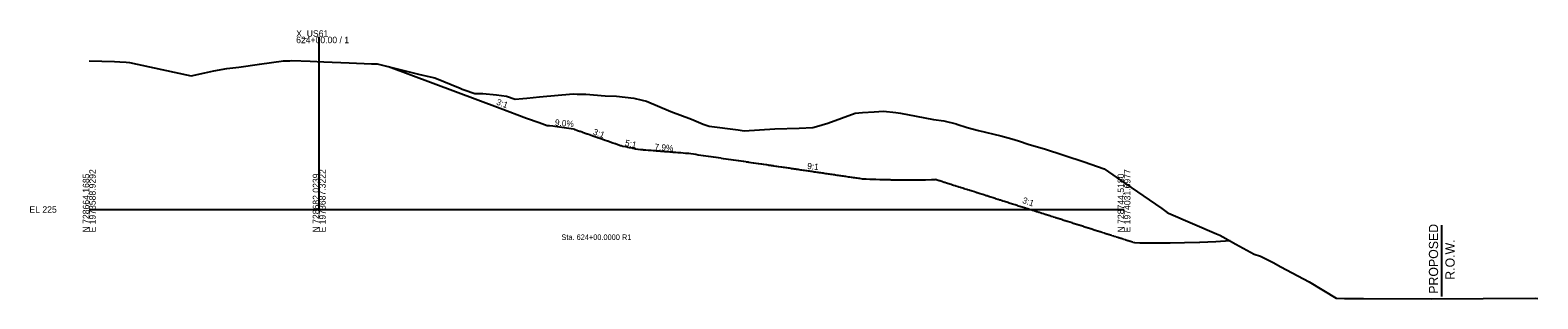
# Model space of a CAD drawing. Extents: x -26 to 630, y -39 to 9098.
# Drawn here: x -26 to 630, y -39 to 78 of the extents above; entities that cross this region are included whole.
import ezdxf

# ---------------------------------------------------------------- set-up
doc = ezdxf.new("R2010")
doc.units = 0
for name, color, linetype in [('CONST_DCH', 7, 'Continuous'), ('Default', 7, 'Continuous'), ('Draft_XS_Grid', 7, 'Continuous'), ('Draft_XS_Text', 7, 'Continuous'), ('DTM_X_FLOW_ARROWS', 7, 'Continuous'), ('DTM_X_GROUND', 7, 'Continuous'), ('XS_CELL', 7, 'Continuous'), ('XS_P_GROUND', 7, 'Continuous'), ('XS_P_ROW', 7, 'Continuous'), ('XS_P_TX_FS_BS', 7, 'Continuous')]:
    doc.layers.add(name, color=color, linetype=linetype)

msp = doc.modelspace()

# ---------------------------------------------------------------- linework, layer by layer
at = {"layer": 'DTM_X_GROUND'}
msp.add_lwpolyline([(0, 64.48), (10.96, 64.2), (13.31, 64.15), (16.1, 63.91), (17.53, 63.79), (20.8, 63.08), (44.32, 58.06), (50.31, 59.32), (54.16, 60.13), (59.81, 61.19), (65.07, 61.81), (74.07, 63.05), (84.46, 64.48), (87.2, 64.59), (88.13, 64.63), (96.02, 64.37), (102, 64.17), (113.06, 63.68), (122.74, 63.25), (123.28, 63.24), (125.23, 63.19), (143.22, 58.82), (148.23, 57.66), (150.24, 57.15), (161.3, 52.65), (162.21, 52.3), (163.05, 51.98), (167.75, 50.3), (171.13, 50.4), (177.05, 49.82), (181.48, 49.14), (185.25, 47.91), (188.63, 48.18), (190.36, 48.32), (195.82, 48.85), (210.42, 50.18), (212.18, 50.12), (215.92, 50.01), (224.35, 49.34), (229.31, 49.18), (236.83, 48.34), (240.5, 47.48), (242.4, 47.03), (252.93, 42.49), (261.95, 39.24), (266.97, 37.11), (269.53, 36.23), (282.23, 34.55), (284.75, 34.21), (298.13, 34.97), (308.68, 35.33), (314.62, 35.55), (316.28, 36.04), (321.16, 37.49), (333.03, 41.83), (336.21, 42.06), (341.37, 42.44), (345.38, 42.75), (350.7, 42.06), (352.78, 41.8), (359.57, 40.51), (367.19, 39.01), (371.71, 38.42), (376.94, 37.13), (377.24, 37.03), (381.86, 35.59), (386.79, 34.35), (396.4, 32.02), (401.21, 30.65), (404.1, 29.78), (408.75, 28.22), (415.35, 26.37), (432.61, 20.7), (441.38, 17.61), (450.42, 11.4), (466.46, 0.38), (468.82, -1.32), (469.36, -1.66), (490.18, -10.6), (491.62, -11.17), (492.92, -11.9), (498.61, -15.09), (506.62, -19.39), (509.37, -20.29), (514.9, -23.06), (518.23, -24.95), (530.49, -31.39), (542.25, -38.58), (545.81, -38.59), (550.25, -38.61), (551.07, -38.62), (553.13, -38.68), (554.11, -38.68), (583.63, -38.79), (628.84, -38.52), (629.96, -38.61)], dxfattribs=at)
at = {"layer": 'XS_CELL'}
for p, q in [((100, 0), (100, 75)), ((0, 0), (100, 0)), ((100, 0), (450, 0))]:
    msp.add_line(p, q, dxfattribs=at)
at = {"layer": 'XS_P_GROUND'}
for points in [[(130.08, 62.01), (178.64, 43.98), (190.22, 39.64), (195.63, 37.81), (199.21, 36.5)], [(199.21, 36.5), (200.07, 36.47), (200.11, 36.47), (201.64, 36.29), (202.53, 36.17)], [(202.53, 36.17), (210.65, 34.94), (210.65, 34.94), (210.65, 34.94), (211.08, 34.79), (211.28, 34.72), (212.06, 34.45), (212.37, 34.34), (213.18, 34.06), (213.47, 33.96), (214.3, 33.66), (214.56, 33.57), (215.42, 33.27), (215.66, 33.19), (216.54, 32.88), (216.75, 32.81), (217.66, 32.49), (217.85, 32.42), (218.77, 32.1), (218.94, 32.04), (219.88, 31.71), (220.03, 31.66), (221, 31.32), (221.13, 31.27), (222.11, 30.93), (222.22, 30.89), (223.22, 30.54), (223.32, 30.51), (224.33, 30.15), (224.41, 30.12), (225.44, 29.77), (225.51, 29.74), (226.55, 29.38), (226.6, 29.36), (227.66, 28.99), (227.7, 28.98), (228.76, 28.6), (228.79, 28.59), (229.87, 28.21), (229.89, 28.21), (230.98, 27.83), (230.98, 27.83), (231.29, 27.72), (232.08, 27.55), (232.21, 27.52), (233.17, 27.31), (233.88, 27.16), (234.27, 27.08), (234.79, 26.97), (235.36, 26.85), (236.07, 26.69), (236.46, 26.61), (236.74, 26.55), (237.55, 26.38), (238.64, 26.14), (238.64, 26.14), (238.66, 26.14)], [(238.66, 26.14), (239.74, 26.05), (239.8, 26.05), (240.83, 25.97), (240.95, 25.96), (241.93, 25.88), (242.1, 25.87), (243.02, 25.79), (243.25, 25.78), (244.12, 25.71), (244.4, 25.69), (245.21, 25.62), (245.55, 25.6), (246.31, 25.54), (246.71, 25.5), (247.4, 25.45), (247.86, 25.41), (248.5, 25.36), (249.01, 25.32), (249.59, 25.28), (250.16, 25.23), (250.69, 25.19), (251.31, 25.14), (251.78, 25.1), (252.46, 25.05), (252.88, 25.02), (253.62, 24.96), (253.97, 24.93), (254.77, 24.87), (255.07, 24.85), (255.92, 24.78), (256.16, 24.76), (257.07, 24.69), (257.25, 24.67), (258.22, 24.6), (258.35, 24.59), (259.37, 24.51), (259.44, 24.5), (260.53, 24.42), (260.54, 24.41), (260.78, 24.4), (261.63, 24.27), (261.63, 24.27), (262.71, 24.11), (262.73, 24.11), (263.79, 23.95), (263.82, 23.95), (264.88, 23.79), (264.92, 23.79), (265.96, 23.64), (266.01, 23.63), (267.05, 23.48), (267.11, 23.47), (268.13, 23.32), (268.2, 23.31), (269.22, 23.16), (269.3, 23.15), (270.3, 23), (270.39, 22.99), (271.39, 22.84), (271.49, 22.83), (272.47, 22.68), (272.58, 22.67), (273.55, 22.52), (273.68, 22.51), (274.64, 22.36), (274.77, 22.34), (275.72, 22.2), (275.87, 22.18), (276.81, 22.05), (276.96, 22.02), (277.89, 21.89), (278.05, 21.86), (278.98, 21.73), (279.15, 21.7), (280.06, 21.57), (280.24, 21.54), (281.15, 21.41), (281.34, 21.38), (282.24, 21.25), (282.43, 21.22), (283.32, 21.09), (283.53, 21.06), (284.41, 20.93), (284.62, 20.9), (285.49, 20.77), (285.72, 20.74), (286.58, 20.61), (286.81, 20.58), (287.66, 20.45), (287.91, 20.42), (288.75, 20.3), (289, 20.26), (289.83, 20.14), (290.1, 20.1), (290.92, 19.98), (291.19, 19.94), (292, 19.82), (292.29, 19.78), (293.09, 19.66), (293.38, 19.62), (294.18, 19.5), (294.48, 19.46), (295.26, 19.34), (295.57, 19.3), (296.35, 19.18), (296.66, 19.14), (297.43, 19.02), (297.76, 18.97), (298.52, 18.86), (298.85, 18.81), (299.61, 18.7), (299.95, 18.65), (300.69, 18.54), (301.04, 18.49), (301.78, 18.39), (302.14, 18.33), (302.86, 18.23), (303.23, 18.17), (303.95, 18.07), (304.33, 18.01), (305.04, 17.91), (305.42, 17.85), (306.12, 17.75), (306.52, 17.69), (307.21, 17.59), (307.61, 17.53), (308.3, 17.43), (308.71, 17.37), (309.38, 17.27), (309.8, 17.21), (310.47, 17.11), (310.9, 17.05), (311.56, 16.95), (311.99, 16.89), (312.64, 16.79), (313.09, 16.73), (313.73, 16.63), (314.18, 16.57), (314.82, 16.47), (315.27, 16.41), (315.9, 16.31), (316.37, 16.25), (316.99, 16.16), (317.46, 16.09), (318.08, 16), (318.56, 15.93), (319.16, 15.84), (319.65, 15.77), (320.25, 15.68), (320.75, 15.6), (321.34, 15.52), (321.84, 15.44), (322.42, 15.36), (322.94, 15.28), (323.51, 15.2), (324.03, 15.12), (324.6, 15.04), (325.13, 14.96), (325.69, 14.88), (326.22, 14.8), (326.77, 14.72), (327.32, 14.64), (327.86, 14.56), (328.41, 14.48), (328.95, 14.4), (329.51, 14.32), (330.03, 14.24), (330.6, 14.16), (331.36, 14.05), (331.7, 14), (332.28, 13.91), (332.79, 13.84), (333.38, 13.75), (333.88, 13.68), (334.49, 13.59), (334.98, 13.52), (335.59, 13.43), (336.07, 13.36), (336.2, 13.34), (336.3, 13.32), (337.47, 13.3), (337.92, 13.25), (339.45, 13.22), (340, 13.16), (341.61, 13.14), (342.12, 13.09), (343.8, 13.07), (344.29, 13.02), (346.05, 13), (346.5, 12.97), (348.35, 12.95), (348.76, 12.92), (350.71, 12.91), (351.08, 12.89), (353.13, 12.89), (353.45, 12.86), (355.62, 12.87), (355.89, 12.85), (358.17, 12.87), (358.39, 12.85), (360.8, 12.88), (360.97, 12.87), (363.52, 12.91), (363.62, 12.9), (366.32, 12.95), (366.36, 12.95), (367.96, 12.98)], [(496.13, -13.64), (490, -14.01), (489.9, -14.01), (483.03, -14.33), (482.83, -14.33), (476.34, -14.54), (470.1, -14.65), (469.83, -14.66), (463.62, -14.68), (463.39, -14.68), (457.12, -14.6), (456.92, -14.6), (454.74, -14.53), (454.65, -14.52), (453.9, -14.28), (453.64, -14.2), (452.88, -13.96), (452.63, -13.88), (451.86, -13.64), (451.62, -13.56), (450.85, -13.32), (450.61, -13.24), (449.83, -12.99), (449.6, -12.92), (448.81, -12.67), (448.59, -12.6), (447.79, -12.35), (447.58, -12.28), (447.38, -12.22), (447.33, -12.2), (446.72, -12.01), (446.57, -11.96), (446.47, -11.93), (446.44, -11.92), (445.73, -11.69), (445.56, -11.64), (444.74, -11.38), (444.55, -11.32), (443.72, -11.05), (443.54, -11), (442.7, -10.73), (442.53, -10.68), (441.68, -10.41), (441.52, -10.36), (440.66, -10.08), (440.51, -10.04), (439.65, -9.76), (439.5, -9.72), (438.63, -9.44), (438.49, -9.4), (437.61, -9.11), (437.48, -9.08), (436.59, -8.79), (436.47, -8.76), (435.57, -8.47), (435.46, -8.43), (434.55, -8.14), (434.45, -8.11), (433.53, -7.82), (433.44, -7.79), (432.51, -7.5), (432.43, -7.47), (431.49, -7.17), (431.42, -7.15), (430.47, -6.85), (430.41, -6.83), (429.45, -6.53), (429.4, -6.51), (428.43, -6.2), (428.39, -6.19), (427.41, -5.88), (427.38, -5.87), (426.38, -5.55), (426.37, -5.55), (425.36, -5.23), (425.36, -5.23), (425.31, -5.21), (424.35, -4.91), (424.33, -4.9), (423.34, -4.59), (423.3, -4.57), (422.33, -4.27), (422.27, -4.25), (421.32, -3.95), (421.24, -3.92), (420.31, -3.63), (420.3, -3.62), (420.18, -3.59), (420.09, -3.56), (419.3, -3.31), (419.18, -3.27), (418.29, -2.99), (418.15, -2.94), (417.28, -2.67), (417.12, -2.61), (416.27, -2.35), (416.09, -2.29), (415.26, -2.02), (415.06, -1.96), (414.25, -1.7), (414.03, -1.63), (413.24, -1.38), (413, -1.31), (412.23, -1.06), (411.96, -0.98), (411.22, -0.74), (410.92, -0.65), (410.21, -0.42), (409.89, -0.32), (409.2, -0.1), (408.85, 0.01), (408.19, 0.22), (407.81, 0.34), (407.18, 0.54), (406.77, 0.67), (406.17, 0.86), (405.73, 1), (405.16, 1.18), (404.69, 1.33), (404.15, 1.5), (403.64, 1.66), (403.14, 1.82), (402.6, 1.99), (402.13, 2.14), (401.55, 2.33), (401.12, 2.46), (400.51, 2.66), (400.11, 2.78), (399.46, 2.99), (399.1, 3.1), (398.41, 3.32), (398.09, 3.42), (397.35, 3.66), (397.08, 3.74), (396.3, 3.99), (396.07, 4.06), (395.99, 4.09), (395.97, 4.1), (395.22, 4.33), (395.06, 4.39), (394.18, 4.66), (394.05, 4.71), (393.94, 4.74), (393.93, 4.74), (393.11, 5), (393.04, 5.03), (392.06, 5.34), (392.03, 5.35), (391.51, 5.51), (391.24, 5.6), (391.16, 5.62), (391.02, 5.67), (390.45, 5.85), (390.01, 5.99), (389.72, 6.08), (389, 6.31), (388.59, 6.44), (387.99, 6.63), (387.42, 6.81), (387.03, 6.93), (387.01, 6.94), (386.98, 6.95), (386.19, 7.2), (385.97, 7.27), (385.77, 7.33), (384.96, 7.59), (384.91, 7.61), (383.95, 7.91), (383.58, 8.03), (382.94, 8.23), (382.66, 8.32), (381.93, 8.55), (381.71, 8.62), (380.92, 8.87), (380.73, 8.93), (380.55, 8.99), (380.23, 9.09), (379.91, 9.19), (379.21, 9.42), (378.9, 9.51), (378.15, 9.75), (377.89, 9.83), (377.82, 9.86), (376.88, 10.15), (376.6, 10.24), (375.87, 10.47), (375.42, 10.62), (374.86, 10.8), (374.29, 10.98), (373.85, 11.12), (373.18, 11.33), (372.84, 11.44), (372.08, 11.68), (371.83, 11.76), (370.99, 12.02), (370.82, 12.08), (369.84, 12.39), (369.81, 12.4), (369.65, 12.45), (368.8, 12.72), (368.73, 12.74), (368.49, 12.82), (367.96, 12.98)]]:
    msp.add_lwpolyline(points, dxfattribs=at)
at = {"layer": 'XS_P_ROW'}
msp.add_line((588, -6.82), (588, -37.83), dxfattribs=at)

# ---------------------------------------------------------------- texts
at = {"layer": 'CONST_DCH'}
for p in [(190.22, 39.64), (199.21, 36.5), (199.21, 36.5), (202.53, 36.17), (210.49, 35.46), (238.66, 26.14), (238.66, 26.14), (260.78, 24.4)]:
    msp.add_text('X', height=0.001, dxfattribs=at).set_placement(p)
at = {"layer": 'Default'}
for p in [(130.08, 62.01), (367.96, 12.98)]:
    msp.add_text('X', height=0.001, dxfattribs=at).set_placement(p)
at = {"layer": 'Draft_XS_Grid'}
msp.add_text('-', height=0.0001, dxfattribs=at).set_placement((0, 0))
at = {"layer": 'Draft_XS_Text'}
msp.add_text('Sta. 624+00.0000 R1', height=2.4, dxfattribs=at).set_placement((205.34, -13.25))
at = {"layer": 'DTM_X_FLOW_ARROWS'}
for p in [(200.11, 36.47), (231.29, 27.72)]:
    msp.add_text('X', height=0.001, dxfattribs=at).set_placement(p)
at = {"layer": 'XS_CELL'}
for s, p in [('X_US61', (90, 75)), ('624+00.00 / 1', (90, 72.2)), ('EL 225', (-26, -1.4))]:
    msp.add_text(s, height=2.8, dxfattribs=at).set_placement(p)
for s, p in [('N 728664.1685', (0, -10)), ('E 1973588.9292', (2.8, -10)), ('N 728682.0239', (100, -10)), ('E 1973687.3222', (102.8, -10)), ('N 728744.5180', (450, -10)), ('E 1974031.6977', (452.8, -10))]:
    msp.add_text(s, height=2.8, rotation=90, dxfattribs=at).set_placement(p)
at = {"layer": 'XS_P_ROW'}
for s, p in [('PROPOSED', (586.58, -36.59)), ('R.O.W.', (593.78, -30.52))]:
    msp.add_text(s, height=4, rotation=90, dxfattribs=at).set_placement(p)
at = {"layer": 'XS_P_TX_FS_BS'}
for s, rotation, p in [('3:1', 339.59227, (176.79, 45.62)), ('9.0%', 354.86001, (202.42, 36.48)), ('3:1', 339.59165, (218.84, 32.67)), ('5:1', 347.89859, (232.79, 27.7)), ('7.9%', 355.49539, (245.73, 25.88)), ('9:1', 353.92247, (312.12, 17.6)), ('3:1', 340.70774, (405.56, 2.9))]:
    msp.add_text(s, height=2.7, rotation=rotation, dxfattribs=at).set_placement(p)

doc.saveas('drawing.dxf')
